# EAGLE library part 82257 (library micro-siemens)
MICROPROCESSOR/PERIPHERAL DEVICE
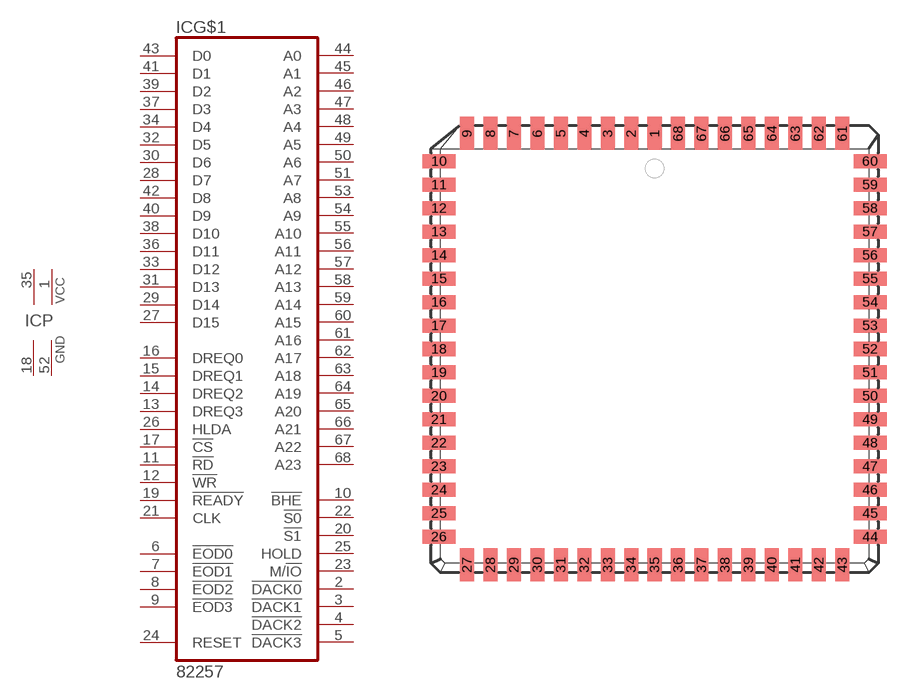
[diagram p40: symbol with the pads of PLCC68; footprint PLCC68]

Designator prefix IC; gates G$1=82257 P=2VCC2GND

## 82257 (OC_FARNELL: unknown; OC_NEWARK: unknown)  [PLCC68]
1  P:VCC  pwr
2  G$1:!DACK0  out
3  G$1:!DACK1  out
4  G$1:!DACK2  out
5  G$1:!DACK3  out
6  G$1:!EOD0
7  G$1:!EOD1
8  G$1:!EOD2
9  G$1:!EOD3
10  G$1:!BHE
11  G$1:!RD  in
12  G$1:!WR  in
13  G$1:DREQ3  in
14  G$1:DREQ2  in
15  G$1:DREQ1  in
16  G$1:DREQ0  in
17  G$1:!CS  in
18  P:GND  pwr
19  G$1:!READY  in
20  G$1:!S1
21  G$1:CLK  in
22  G$1:!S0
23  G$1:M/!IO  out
24  G$1:RESET  in
25  G$1:HOLD  out
26  G$1:HLDA  in
27  G$1:D15
28  G$1:D7
29  G$1:D14
30  G$1:D6
31  G$1:D13
32  G$1:D5
33  G$1:D12
34  G$1:D4
35  P:VCC  pwr
36  G$1:D11
37  G$1:D3
38  G$1:D10
39  G$1:D2
40  G$1:D9
41  G$1:D1
42  G$1:D8
43  G$1:D0
44  G$1:A0
45  G$1:A1
46  G$1:A2
47  G$1:A3
48  G$1:A4
49  G$1:A5
50  G$1:A6
51  G$1:A7
52  P:GND  pwr
53  G$1:A8  out
54  G$1:A9  out
55  G$1:A10  out
56  G$1:A11  out
57  G$1:A12  out
58  G$1:A13  out
59  G$1:A14  out
60  G$1:A15  out
61  G$1:A16  out
62  G$1:A17  out
63  G$1:A18  out
64  G$1:A19  out
65  G$1:A20  out
66  G$1:A21  out
67  G$1:A22  out
68  G$1:A23  out

## Footprint PLCC68 (pad centres in mm)
PLASTIC LEADED CHIP CARRIER square
smd 0.76 x 1.8: 1 0,11.67; 2 -1.27,11.67; 3 -2.54,11.67; 4 -3.81,11.67; 5 -5.08,11.67; 6 -6.35,11.67; 7 -7.62,11.67; 8 -8.89,11.67; 9 -10.16,11.67; 27 -10.16,-11.67; 28 -8.89,-11.67; 29 -7.62,-11.67; 30 -6.35,-11.67; 31 -5.08,-11.67; 32 -3.81,-11.67; 33 -2.54,-11.67; 34 -1.27,-11.67; 35 0,-11.67; 36 1.27,-11.67; 37 2.54,-11.67; 38 3.81,-11.67; 39 5.08,-11.67; 40 6.35,-11.67; 41 7.62,-11.67; 42 8.89,-11.67; 43 10.16,-11.67; 61 10.16,11.67; 62 8.89,11.67; 63 7.62,11.67; 64 6.35,11.67; 65 5.08,11.67; 66 3.81,11.67; 67 2.54,11.67; 68 1.27,11.67
smd 1.8 x 0.76: 10 -11.67,10.16; 11 -11.67,8.89; 12 -11.67,7.62; 13 -11.67,6.35; 14 -11.67,5.08; 15 -11.67,3.81; 16 -11.67,2.54; 17 -11.67,1.27; 18 -11.67,0; 19 -11.67,-1.27; 20 -11.67,-2.54; 21 -11.67,-3.81; 22 -11.67,-5.08; 23 -11.67,-6.35; 24 -11.67,-7.62; 25 -11.67,-8.89; 26 -11.67,-10.16; 44 11.67,-10.16; 45 11.67,-8.89; 46 11.67,-7.62; 47 11.67,-6.35; 48 11.67,-5.08; 49 11.67,-3.81; 50 11.67,-2.54; 51 11.67,-1.27; 52 11.67,0; 53 11.67,1.27; 54 11.67,2.54; 55 11.67,3.81; 56 11.67,5.08; 57 11.67,6.35; 58 11.67,7.62; 59 11.67,8.89; 60 11.67,10.16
